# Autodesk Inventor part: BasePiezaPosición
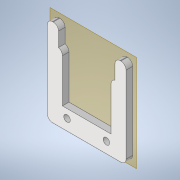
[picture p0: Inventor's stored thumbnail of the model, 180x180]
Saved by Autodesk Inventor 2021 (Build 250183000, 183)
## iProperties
Created: 2021-02
Part Number: BasePiezaPosición
Material: Genérico
Document SubType Name: Modeling
Designer: ATOUZA
Density: 1 g/cm^3
Appearance: Valor por defecto
Author: ATOUZA
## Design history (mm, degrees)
node "Plano de trabajo1"
node "Plano de trabajo2"
sketch "Boceto1"
  geometry: L1 (-26, -33.365)-(26, -33.365) reference; L2 (30, -29.365)-(30, 29.365) reference; L3 (-30, 29.365)-(-30, -29.365) reference; L4 (18.5, -18.5)-(-18.5, -18.5); L5 (-18.5, -18.5)-(-18.5, 18.5); L6 (18.5, 18.5)-(18.5, -18.5); L7 (18.5, -18.5)-(-18.5, 18.5); L8 (-18.5, -18.5)-(18.5, 18.5); L9 (-18.5, 18.5)-(-21.5, 18.5); L10 (-21.5, 18.5)-(-21.5, 33.365); L11 (18.5, 18.5)-(21.5, 18.5); L12 (21.5, 18.5)-(21.5, 33.365); L13 (26, 33.365)-(21.5, 33.365); L14 (-21.5, 33.365)-(-26, 33.365); C1 r 2.5 at (-15, -25) reference; C2 r 2.5 at (15, -25) reference; A1 r 4 centre (-26, -29.365) between (-30, -29.365) and (-26, -33.365) reference; A2 r 4 centre (26, -29.365) between (26, -33.365) and (30, -29.365) reference; A3 r 4 centre (26, 29.365) between (30, 29.365) and (26, 33.365) reference; A4 r 4 centre (-26, 29.365) between (-26, 33.365) and (-30, 29.365) reference; 1 further point
  constraints: 22 end point, 2 midpoint, 1 horizontal, 1 parallel, 1 perpendicular, 1 point on line
  dimensions: "d4" = 37 distance of L4.end L5.end; "d5" = 37 distance of L4.start L4.end; "d6" = 3 distance between parallel lines of L10 L5; "d7" = 3 distance between parallel lines of L12 L6
extrude "Extrusión1" new body sketch "Boceto1" distance "d8" = 5; taper "d9" = 0 deg
fillet "Empalme1" dims "d10" = 4
node "Sólido1"
